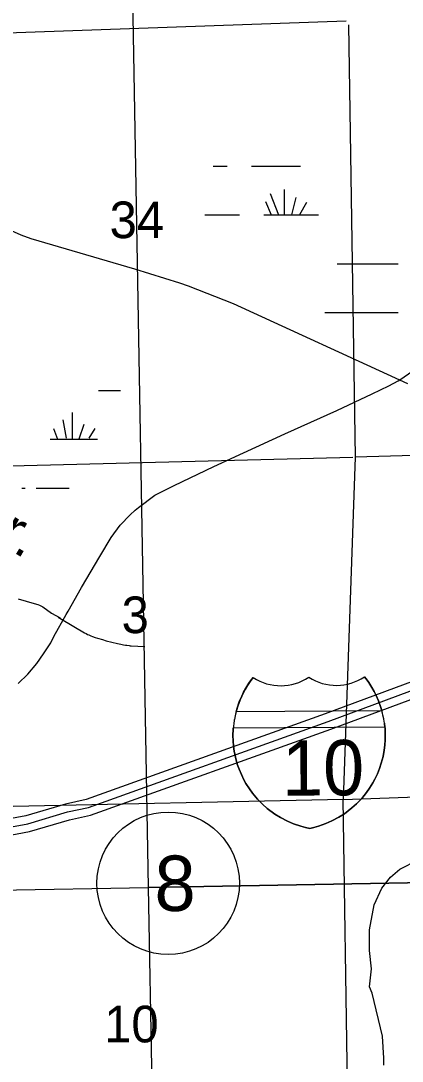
# Model space of a CAD drawing. Extents: x 2480962 to 2688785, y 277103 to 599240.
# Drawn here: x 2598432 to 2603117, y 458082 to 470861 of the extents above; entities that cross this region are included whole.
import ezdxf

# ---------------------------------------------------------------- set-up
doc = ezdxf.new("R2010")
doc.units = 0
for name, color, linetype in [('County Routes Highway Center Lines', 7, 'Continuous'), ('Divided_Highway', 7, 'Continuous'), ('Interstate Divided Highway Outline and Fill', 7, 'Continuous'), ('Interstate Highway Center Lines', 7, 'Continuous'), ('Lakes and Ponds Text', 7, 'Continuous'), ('Local Roads Improved', 7, 'Continuous'), ('Narrow River Creek and Branch and Slough', 7, 'Continuous'), ('Planning Number Interstates', 7, 'Continuous'), ('Roadshields Interstates', 7, 'Continuous'), ('Section Lines', 7, 'Continuous'), ('Section Numbers', 7, 'Continuous'), ('Swamps', 7, 'Continuous'), ('Township and Range lines', 7, 'Continuous')]:
    doc.layers.add(name, color=color, linetype=linetype)

msp = doc.modelspace()

# ---------------------------------------------------------------- linework, layer by layer
at = {"layer": 'County Routes Highway Center Lines'}
msp.add_lwpolyline([(2598401.288, 462722.583), (2598517.011, 462833.767), (2598628.195, 462965.373), (2598709.882, 463085.634), (2598800.644, 463221.778), (2598836.949, 463298.926), (2598988.977, 463566.676), (2599011.668, 463607.52), (2599177.31, 463900.229), (2599401.948, 464281.433), (2599540.361, 464512.878), (2599653.814, 464667.175), (2599776.344, 464794.243), (2599837.609, 464848.7), (2599878.452, 464882.736), (2600078.13, 465032.495), (2600316.382, 465152.755), (2600801.963, 465386.47), (2601167.283, 465554.381), (2601673.286, 465788.095), (2602315.432, 466076.266), (2602746.555, 466280.483), (2602953.04, 466378.053), (2603066.494, 466439.318), (2603089.184, 466452.932), (2603245.75, 466561.847)], dxfattribs=at)
at = {"layer": 'Divided_Highway'}
for p, q in [((2600001.432, 460214.017), (2599203.547, 505666.246)), ((2600001.432, 460214.017), (2639463.689, 460928.527)), ((2639463.689, 460928.527), (2600001.432, 460214.017)), ((2600001.432, 460214.017), (2639463.689, 460928.527)), ((2639463.689, 460928.527), (2600001.432, 460214.017)), ((2639463.689, 460928.527), (2600001.432, 460214.017)), ((2560538.616, 459542.689), (2600001.432, 460214.017)), ((2600799.421, 414762.355), (2600001.432, 460214.017))]:
    msp.add_line(p, q, dxfattribs=at)
at = {"layer": 'Interstate Divided Highway Outline and Fill'}
for points in [[(2615860.872, 462666.936), (2614846.606, 462746.8), (2613745.507, 462882.442), (2612882.696, 463010.266), (2611905.625, 463162.433), (2611017.317, 463282.475), (2609241.502, 463562.445), (2607797.149, 463787.123), (2607394.649, 463819.98), (2606934.367, 463795.754), (2606632.043, 463795.754), (2606262.446, 463730.048), (2605758.864, 463632.581), (2605136.098, 463422.296), (2604358.389, 463157.715), (2602172.63, 462349.064), (2599233.85, 461294.936), (2598980.548, 461239.526), (2598493.922, 461095.932), (2597890.055, 460984.693)], [(2597927.786, 460788.279), (2598540.468, 460901.141), (2599030.283, 461045.677), (2599289.213, 461102.318), (2602241.092, 462161.144), (2604425.306, 462969.223), (2605200.298, 463232.88), (2605810.089, 463438.784), (2606298.954, 463533.403), (2606649.683, 463595.754), (2606939.626, 463595.754), (2607391.756, 463619.551), (2607773.611, 463588.379), (2609210.558, 463364.854), (2610988.348, 463084.572), (2611876.842, 462964.505), (2612852.652, 462812.534), (2613718.622, 462684.242), (2614826.52, 462547.762), (2615845.172, 462467.553)]]:
    msp.add_lwpolyline(points, dxfattribs=at)
at = {"layer": 'Interstate Highway Center Lines'}
msp.add_lwpolyline([(2597908.921, 460886.486), (2598517.195, 460998.537), (2599005.416, 461142.602), (2599261.531, 461198.627), (2602206.861, 462255.104), (2604391.847, 463063.469), (2605168.198, 463327.588), (2605784.476, 463535.682), (2606280.7, 463631.725), (2606640.863, 463695.754), (2606936.997, 463695.754), (2607393.203, 463719.765), (2607785.38, 463687.751), (2609226.03, 463463.65), (2611002.832, 463183.523), (2611891.233, 463063.469), (2612867.674, 462911.4), (2613732.065, 462783.342), (2614836.563, 462647.281), (2615853.022, 462567.245)], dxfattribs=at)
at = {"layer": 'Local Roads Improved'}
for p, q in [((2599832.906, 467810.738), (2598557.415, 468183.267)), ((2600386.377, 467636.456), (2599832.906, 467810.738)), ((2603185.414, 466401.932), (2601043.005, 467383.746))]:
    msp.add_line(p, q, dxfattribs=at)
for points in [[(2598557.415, 468183.267), (2598434.957, 468226.107), (2598317.647, 468281.513), (2598206.772, 468348.876), (2598103.545, 468427.461), (2598012.204, 468513.169)], [(2601043.005, 467383.746), (2600493.424, 467601.572), (2600386.377, 467636.456)], [(2602892.661, 458031.517), (2602892.661, 458120.751), (2602876.437, 458388.451), (2602746.642, 458915.74), (2602714.194, 458996.861), (2602722.306, 459069.871), (2602738.53, 459215.889), (2602714.194, 459443.029), (2602714.194, 459694.505), (2602770.979, 460002.766), (2602868.324, 460205.569), (2602973.782, 460343.476), (2603087.352, 460440.821), (2603314.492, 460554.391), (2603484.847, 460627.401), (2603525.407, 460651.737), (2603671.426, 460830.204), (2603768.771, 460903.213), (2603979.687, 461024.895), (2604109.481, 461106.016), (2604231.163, 461284.483), (2604547.536, 461844.221), (2604644.882, 462047.024), (2604596.209, 462160.594)]]:
    msp.add_lwpolyline(points, dxfattribs=at)
at = {"layer": 'Narrow River Creek and Branch and Slough'}
for points in [[(2598398.095, 463759.781), (2598496.318, 463732.49), (2598568.003, 463712.696), (2598639.655, 463692.735), (2598663.203, 463684.18), (2598701.462, 463662.737), (2598810.552, 463584.847), (2598862.787, 463555.751), (2598915.023, 463526.655)], [(2598889.576, 463535.082), (2598930.378, 463510.315), (2599216.178, 463343.781), (2599234.903, 463333.094), (2599251.698, 463324.524), (2599266.667, 463317.554), (2599293.375, 463306.374), (2599313.745, 463298.69), (2599344.666, 463287.992), (2599375.804, 463277.918), (2599436.345, 463259.532), (2599481.904, 463246.791), (2599550.621, 463229.263), (2599619.954, 463213.51), (2599662.136, 463204.319), (2599693.797, 463197.691), (2599717.597, 463193.221), (2599735.493, 463190.301), (2599762.436, 463186.84), (2599775.96, 463185.608), (2599789.528, 463184.761), (2599871.498, 463180.894), (2599953.468, 463177.026)]]:
    msp.add_lwpolyline(points, dxfattribs=at)
at = {"layer": 'Planning Number Interstates'}
msp.add_circle((2600242.272, 460266.991), 875, dxfattribs=at)
at = {"layer": 'Roadshields Interstates'}
for p, q in [((2602867.942, 462383.626), (2601076.702, 462373.203)), ((2601076.702, 462373.203), (2601078.145, 462378.617)), ((2602898.798, 462233.799), (2602904.803, 462183.833)), ((2602904.803, 462183.833), (2601042.171, 462173.014))]:
    msp.add_line(p, q, dxfattribs=at)
for points in [[(2601285.733, 462794.824), (2601254.65, 462753.399), (2601234.389, 462724.159), (2601196.399, 462663.527), (2601168.477, 462612.881), (2601145.348, 462565.749), (2601116.294, 462497.308), (2601088.576, 462417.087), (2601069.361, 462346.073), (2601064.657, 462323.132)], [(2601078.145, 462378.617), (2601076.776, 462373.235), (2601088.576, 462417.087), (2601116.294, 462497.308), (2601145.348, 462565.749), (2601168.477, 462612.881), (2601196.399, 462663.527), (2601234.389, 462724.159), (2601254.65, 462753.399), (2601285.733, 462794.824)], [(2602880.57, 462333.698), (2602875.601, 462356.575), (2602855.562, 462427.36), (2602826.913, 462507.253), (2602797.066, 462575.352), (2602773.39, 462622.212), (2602744.881, 462672.53), (2602706.188, 462732.716), (2602685.588, 462761.718), (2602654.026, 462802.779)], [(2602654.026, 462802.779), (2602685.588, 462761.718), (2602706.188, 462732.716), (2602744.881, 462672.53), (2602773.39, 462622.212), (2602797.066, 462575.352), (2602826.913, 462507.253), (2602855.562, 462427.36), (2602867.942, 462383.626)], [(2601047.594, 462223.046), (2601045.087, 462205.328), (2601041.114, 462161.307), (2601038.214, 462083.994), (2601039.789, 462018.677), (2601045.18, 461952.328), (2601053.731, 461890.249), (2601068.911, 461814.337), (2601091.64, 461731.531), (2601113.437, 461668.652), (2601140.999, 461602.258), (2601172.624, 461537.708), (2601197.55, 461493.008), (2601240.136, 461425.853), (2601276.448, 461375.654), (2601337.933, 461301.831), (2601401.191, 461237.246), (2601458.997, 461186.191), (2601552.814, 461116.394), (2601622.259, 461073.447), (2601707.202, 461029.515), (2601781.142, 460998.14), (2601870.505, 460967.941), (2601930.089, 460952.183), (2601980.678, 460941.421)], [(2601054.676, 462273.088), (2601047.594, 462223.046)], [(2601064.657, 462323.132), (2601055.306, 462277.538), (2601054.676, 462273.088)], [(2601980.678, 460941.421), (2602031.139, 460952.77), (2602090.535, 460969.22), (2602179.541, 461000.456), (2602253.111, 461032.689), (2602337.539, 461077.606), (2602406.479, 461121.358), (2602499.478, 461192.24), (2602556.687, 461243.964), (2602619.189, 461309.28), (2602679.812, 461383.813), (2602715.537, 461434.431), (2602757.34, 461502.077), (2602781.745, 461547.063), (2602812.617, 461611.977), (2602839.405, 461678.687), (2602860.47, 461741.814), (2602882.234, 461824.879), (2602896.53, 461900.963), (2602904.359, 461963.137), (2602908.978, 462029.544), (2602909.794, 462094.875), (2602905.995, 462172.149), (2602901.51, 462216.121), (2602898.798, 462233.799)], [(2601980.678, 460941.421), (2602031.139, 460952.77), (2602090.535, 460969.22), (2602179.541, 461000.456), (2602253.111, 461032.689), (2602337.539, 461077.606), (2602406.479, 461121.358), (2602499.478, 461192.24), (2602556.687, 461243.964), (2602619.189, 461309.28), (2602679.812, 461383.813), (2602715.537, 461434.431), (2602757.34, 461502.077), (2602781.745, 461547.063), (2602812.617, 461611.977), (2602839.405, 461678.687), (2602860.47, 461741.814), (2602882.234, 461824.879), (2602896.53, 461900.963), (2602904.359, 461963.137), (2602908.978, 462029.544), (2602909.794, 462094.875), (2602905.995, 462172.149), (2602901.51, 462216.121), (2602898.798, 462233.799)], [(2602891.136, 462283.755), (2602890.453, 462288.207), (2602880.57, 462333.698)], [(2602898.798, 462233.799), (2602891.136, 462283.755)], [(2601042.171, 462173.014), (2601042.56, 462174.298), (2601041.114, 462161.307), (2601038.214, 462083.994), (2601039.789, 462018.677), (2601045.18, 461952.328), (2601053.731, 461890.249), (2601068.911, 461814.337), (2601091.64, 461731.531), (2601113.437, 461668.652), (2601140.999, 461602.258), (2601172.624, 461537.708), (2601197.55, 461493.008), (2601240.136, 461425.853), (2601276.448, 461375.654), (2601337.933, 461301.831), (2601401.191, 461237.246), (2601458.997, 461186.191), (2601552.814, 461116.394), (2601622.259, 461073.447), (2601707.202, 461029.515), (2601781.142, 460998.14), (2601870.505, 460967.941), (2601930.089, 460952.183), (2601980.678, 460941.421)], [(2601980.678, 460941.421), (2601930.089, 460952.183), (2601870.505, 460967.941), (2601781.142, 460998.14), (2601707.202, 461029.515), (2601622.259, 461073.447), (2601552.814, 461116.394), (2601458.997, 461186.191), (2601401.191, 461237.246), (2601337.933, 461301.831), (2601276.448, 461375.654), (2601240.136, 461425.853), (2601197.55, 461493.008), (2601172.624, 461537.708), (2601140.999, 461602.258), (2601113.437, 461668.652), (2601091.64, 461731.531), (2601068.911, 461814.337), (2601053.731, 461890.249), (2601045.18, 461952.328), (2601039.789, 462018.677), (2601038.214, 462083.994), (2601041.114, 462161.307), (2601042.171, 462173.014)], [(2602904.803, 462183.833), (2602905.995, 462172.149), (2602909.794, 462094.875), (2602908.978, 462029.544), (2602904.359, 461963.137), (2602896.53, 461900.963), (2602882.234, 461824.879), (2602860.47, 461741.814), (2602839.405, 461678.687), (2602812.617, 461611.977), (2602781.745, 461547.063), (2602757.34, 461502.077), (2602715.537, 461434.431), (2602679.812, 461383.813), (2602619.189, 461309.28), (2602556.687, 461243.964), (2602499.478, 461192.24), (2602406.479, 461121.358), (2602337.539, 461077.606), (2602253.111, 461032.689), (2602179.541, 461000.456), (2602090.535, 460969.22), (2602031.139, 460952.77), (2601980.678, 460941.421)]]:
    msp.add_lwpolyline(points, dxfattribs=at)
for centre, radius, start, end in [((2602183.358, 462087.173), 1143.022, 141.749164, 165.5082835), ((2601625.806, 463312.577), 619.45, 236.7021696, 303.7426307), ((2601625.806, 463312.577), 619.45, 236.7021696, 303.7426307), ((2601625.806, 463312.577), 619.45, 236.7021696, 303.7426307), ((2602307.92, 463321.235), 623.367, 237.1617529, 303.7258974), ((2602307.92, 463321.235), 623.367, 237.1617529, 303.7258974), ((2602307.92, 463321.235), 623.367, 237.1617529, 303.7258974)]:
    msp.add_arc(centre, radius, start, end, dxfattribs=at)
at = {"layer": 'Section Lines'}
for p, q in [((2597167.141, 470675.982), (2602429.978, 470860.019)), ((2602458.738, 470812.883), (2602539.738, 465500.353)), ((2602539.738, 465500.353), (2602392.033, 461297.774)), ((2602392.033, 461297.774), (2607834.885, 461478.013)), ((2602392.032, 461297.775), (2596990.688, 461181.066)), ((2602470.87, 456008.717), (2602392.032, 461297.775))]:
    msp.add_line(p, q, dxfattribs=at)
at = {"layer": 'Swamps'}
for p, q in [((2601266.712, 469075.977), (2601866.713, 469075.987)), ((2601496.223, 468738.657), (2601599.244, 468475.984)), ((2601665.374, 468786.988), (2601665.378, 468475.985)), ((2601435.813, 468641.998), (2601506.626, 468475.983)), ((2601810.363, 468690.333), (2601756.753, 468475.886)), ((2601943.269, 468629.925), (2601853.55, 468476.118)), ((2602316.726, 467875.998), (2602766.727, 467876.006)), ((2602766.727, 467876.006), (2603066.727, 467876.011)), ((2602166.733, 467275.998), (2602766.734, 467276.008)), ((2602766.734, 467276.008), (2603066.734, 467276.013)), ((2599061.974, 466047.866), (2599061.978, 465721.647)), ((2599206.962, 465902.882), (2599146.554, 465721.648)), ((2599339.867, 465854.556), (2599267.376, 465733.732)), ((2602539.738, 465500.353), (2602392.033, 461297.774))]:
    msp.add_line(p, q, dxfattribs=at)
for points in [[(2600794.567, 469075.968), (2600966.711, 469075.971)], [(2600691.641, 468475.969), (2601116.718, 468475.976)], [(2601416.719, 468475.981), (2602087.593, 468475.993)], [(2599387.49, 466319.032), (2599657.653, 466319.036)], [(2598946.712, 465958.27), (2598989.484, 465733.727)], [(2598831.615, 465852.649), (2598880.744, 465721.644)], [(2598790.662, 465721.642), (2599376.062, 465721.652)], [(2598443.62, 465119.021), (2598487.507, 465119.021)], [(2598622.422, 465121.642), (2599026.072, 465121.648)]]:
    msp.add_lwpolyline(points, dxfattribs=at)
at = {"layer": 'Township and Range lines'}
for p, q in [((2607850.67, 465643.254), (2602539.738, 465500.353)), ((2597223.337, 465365.853), (2602512.466, 465499.664))]:
    msp.add_line(p, q, dxfattribs=at)

# ---------------------------------------------------------------- texts
at = {"layer": 'Lakes and Ponds Text'}
msp.add_text('Br.', height=500, rotation=329.4711611, dxfattribs=at).set_placement((2597744.514, 464682.836))
at = {"layer": 'Planning Number Interstates'}
msp.add_text('8', height=680, dxfattribs=at).set_placement((2600074.22, 459926.993))
at = {"layer": 'Roadshields Interstates'}
msp.add_text('10', height=680, rotation=0.3331112, dxfattribs=at).set_placement((2601640.576, 461342.964))
at = {"layer": 'Section Numbers'}
for s, rotation, p in [('34', 359.9794667, (2599522.627, 468191.463)), ('3', 359.97945, (2599670.01, 463339.687)), ('10', 359.9794278, (2599455.983, 458313.126))]:
    msp.add_text(s, height=450, rotation=rotation, dxfattribs=at).set_placement(p)

doc.saveas('drawing.dxf')
